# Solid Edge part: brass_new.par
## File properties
Author: CADSoft
Template: Sync Iso Part.par
Last saved by: Cadcim
Revision: 8
Application: Solid Edge
Accuracy: 0.990
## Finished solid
Body 1: solid body, 16 faces, 18 edges, 0 vertices.
  Faces by surface: cylinder 9, plane 7
  Edges by curve: circle 14, intersection 4
Bounding box of the edges (mm): 64.000 x 64.000 x 64.000, from (-32, -32, -32) to (32, 32, 32).
Cylindrical faces by radius (mm): R3 x2, R4 x1, R16 x1, R22 x1, R24 x2, R32 x2
Planar faces by outward normal: +x 3, +z 1, -x 3
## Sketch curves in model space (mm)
line (-32, 0, 0) -> (32, 0, 0)
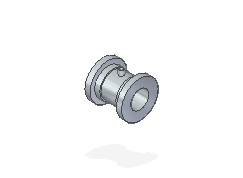
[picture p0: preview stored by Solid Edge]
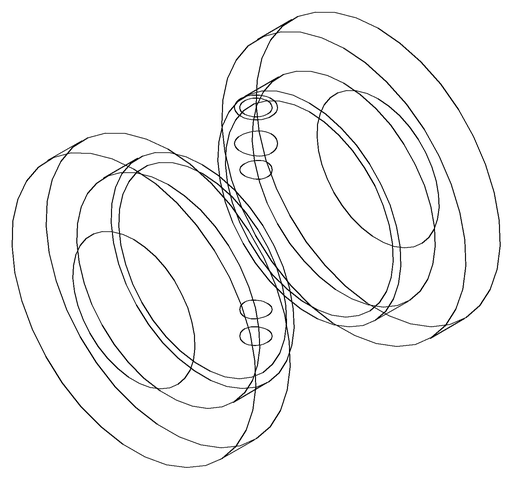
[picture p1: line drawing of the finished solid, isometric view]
